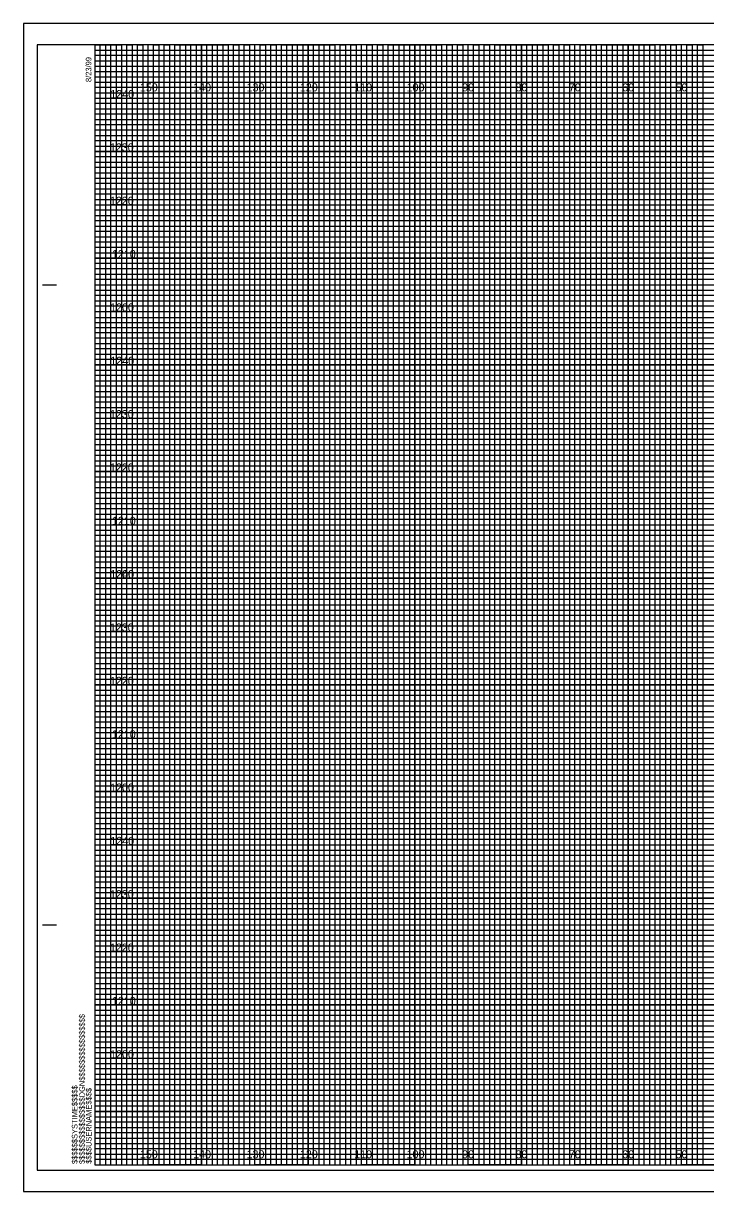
# Model space of a CAD drawing. Extents: x -13 to 323, y -5 to 214.
# Drawn here: x -13.4 to 114.5, y -5 to 214 of the extents above; entities that cross this region are included whole.
import ezdxf

# ---------------------------------------------------------------- set-up
doc = ezdxf.new("R2010")
doc.units = 0
for name, color, linetype in [('Prop XS Elevation Labels', 7, 'Continuous'), ('Prop XS Offset Labels', 7, 'Continuous'), ('Sheet Cross Section CELL', 7, 'Continuous'), ('Sheet Cross Section Grid Major CELL', 7, 'Continuous'), ('Sheet Cross Section Grid Middle CELL', 7, 'Continuous'), ('Sheet Cross Section Grid Minor 1 CELL', 7, 'Continuous'), ('Sheet Cross Section Grid Minor 2 CELL', 7, 'Continuous'), ('Sheet Cutting Line CELL', 7, 'Continuous'), ('Sheet DOT Grid CELL', 7, 'Continuous'), ('Sheet Plot Border Inside CELL', 7, 'Continuous'), ('Sheet Plot Border Outside CELL', 7, 'Continuous')]:
    doc.layers.add(name, color=color, linetype=linetype)

msp = doc.modelspace()

# ---------------------------------------------------------------- linework, layer by layer
at = {"layer": 'Sheet Cross Section CELL'}
for p, q in [((-9.8, 165), (-7.3, 165)), ((-9.7, 165), (-7.2, 165)), ((-9.8, 45), (-7.3, 45)), ((-9.7, 45), (-7.2, 45)), ((0, 0), (0, 0)), ((0, 0), (0, 0)), ((0, 0), (0, 0)), ((0, 0), (0, 0)), ((0, 0), (0, 0)), ((0, 0), (0, 0)), ((0, 0), (0, 0))]:
    msp.add_line(p, q, dxfattribs=at)
msp.add_lwpolyline([(320, 210), (0, 210), (0, 0), (320, 0)], close=True, dxfattribs=at)
at = {"layer": 'Sheet Cross Section Grid Major CELL'}
for p, q in [((10, 210), (0, 210)), ((10, 0), (10, 210)), ((30, 210), (20, 210)), ((20, 210), (20, 0)), ((30, 0), (30, 210)), ((50, 210), (40, 210)), ((40, 210), (40, 0)), ((50, 0), (50, 210)), ((70, 210), (60, 210)), ((60, 210), (60, 0)), ((70, 0), (70, 210)), ((90, 210), (80, 210)), ((80, 210), (80, 0)), ((90, 0), (90, 210)), ((110, 210), (100, 210)), ((100, 210), (100, 0)), ((110, 0), (110, 210)), ((20, 0), (10, 0)), ((40, 0), (30, 0)), ((60, 0), (50, 0)), ((80, 0), (70, 0)), ((100, 0), (90, 0)), ((120, 0), (110, 0))]:
    msp.add_line(p, q, dxfattribs=at)
for points in [[(0, 200), (320, 200), (320, 190), (0, 190)], [(0, 180), (320, 180), (320, 170), (0, 170)], [(0, 160), (320, 160), (320, 150), (0, 150)], [(0, 140), (320, 140), (320, 130), (0, 130)], [(0, 120), (320, 120), (320, 110), (0, 110)], [(0, 100), (320, 100), (320, 90), (0, 90)], [(0, 80), (320, 80), (320, 70), (0, 70)], [(0, 60), (320, 60), (320, 50), (0, 50)], [(0, 40), (320, 40), (320, 30), (0, 30)], [(0, 20), (320, 20), (320, 10), (0, 10)]]:
    msp.add_lwpolyline(points, dxfattribs=at)
at = {"layer": 'Sheet Cross Section Grid Middle CELL'}
for points in [[(0, 210), (5, 210), (5, 0), (15, 0), (15, 210), (25, 210), (25, 0), (35, 0), (35, 210), (45, 210), (45, 0), (55, 0), (55, 210), (65, 210), (65, 0), (75, 0), (75, 210), (85, 210), (85, 0), (95, 0), (95, 210), (105, 210), (105, 0), (115, 0)], [(0, 205), (275, 205)], [(0, 185), (320, 185), (320, 195), (0, 195)], [(0, 165), (320, 165), (320, 175), (0, 175)], [(0, 145), (320, 145), (320, 155), (0, 155)], [(0, 125), (320, 125), (320, 135), (0, 135)], [(0, 105), (320, 105), (320, 115), (0, 115)], [(0, 85), (320, 85), (320, 95), (0, 95)], [(0, 65), (320, 65), (320, 75), (0, 75)], [(0, 45), (320, 45), (320, 55), (0, 55)], [(0, 25), (320, 25), (320, 35), (0, 35)], [(0, 5), (320, 5), (320, 15), (0, 15)]]:
    msp.add_lwpolyline(points, dxfattribs=at)
at = {"layer": 'Sheet Cross Section Grid Minor 1 CELL'}
for p, q in [((0, 209), (260, 209)), ((260, 207.98), (0, 207.98)), ((0, 207.98), (0, 207)), ((0, 207), (260, 207)), ((260, 205.89), (0, 205.89)), ((0, 205.89), (0, 204)), ((0, 204), (320, 204))]:
    msp.add_line(p, q, dxfattribs=at)
for points in [[(0, 203), (270, 203), (320, 203), (320, 202), (0, 202)], [(0, 201), (320, 201), (320, 199), (0, 199)], [(0, 198), (320, 198), (320, 197), (0, 196.98)], [(0, 196), (320, 196), (320, 194), (0, 194)], [(0, 193), (320, 193), (320, 192), (0, 192)], [(0, 191), (320, 191), (320, 189), (0, 189)], [(0, 188), (320, 188), (320, 187), (0, 187)], [(0, 186), (320, 186), (320, 184), (0, 184)], [(0, 183), (320, 183), (320, 182), (0, 182)], [(0, 181), (320, 181), (320, 179), (0, 179)], [(0, 178), (320, 178), (320, 177), (0, 177)], [(0, 176), (320, 176), (320, 173.95), (320, 173), (320, 172), (0, 172)], [(0, 174), (320, 174), (320, 173), (0, 173)], [(0, 171), (320, 171), (320, 169), (0, 169.03)], [(0, 169.03), (320, 169), (320, 168), (0, 168)], [(0, 167), (320, 167), (320, 166), (0, 166)], [(0, 164), (320, 164), (320, 163), (0, 163)], [(0, 162), (320, 162), (320, 161), (0, 161)], [(-0.07, 158.89), (320, 158.89), (320, 157.88), (-0.07, 157.88)], [(0, 157), (320, 157), (320, 156), (0, 156)], [(0, 154), (320, 154), (320, 153), (0, 153)], [(0, 152), (320, 152), (320, 151), (0, 151)], [(0, 149), (320, 149), (320, 148), (0, 148)], [(0, 147), (320, 147), (320, 146), (0, 146)], [(0, 144), (320, 144), (320, 143), (0, 143)], [(0, 142), (320, 142), (320, 141), (0, 141)], [(0, 139), (320, 139), (319.99, 137.98), (0, 138)], [(0, 137), (320, 137), (320, 136), (0, 136)], [(0, 134), (320, 134), (320, 133), (0, 133)], [(0, 132), (320, 132), (320, 131), (0, 131)], [(0, 129), (320, 129), (320, 128), (0, 128)], [(0, 127), (320, 127), (320, 126), (0, 126)], [(0, 124), (320, 124), (320, 123), (0, 123)], [(0, 122), (320, 122), (320, 121), (0, 121)], [(0, 119), (320, 119), (320, 118), (0, 118)], [(0, 116.99), (320.07, 116.91), (320, 116), (0, 116)], [(0, 114), (320, 114), (320, 113), (0, 113)], [(0, 112), (320, 112), (320, 111), (0, 111)], [(0, 109), (320, 109), (320, 108), (0, 108)], [(0, 107), (320, 107), (320, 106), (0, 106)], [(0, 104), (320, 104), (320, 103), (0, 103)], [(0, 102), (320, 102), (320, 101), (0, 101)], [(0, 99), (320, 99), (320, 98), (0, 98)], [(0, 97), (320, 97), (320, 96), (0, 96)], [(0, 94), (320, 94), (320, 93), (0, 93)], [(0, 92), (320, 92), (320, 91), (0, 91)], [(0, 89), (320, 89), (320, 88), (0, 88)], [(0, 87), (320, 87), (320, 86), (0, 86)], [(0, 84), (320, 84), (320, 83), (0, 83)], [(0, 82), (320, 82), (320, 81), (0, 81)], [(0, 79), (320, 79), (319.99, 77.98), (0, 78)], [(0, 77), (320, 77), (320, 76), (0, 76)], [(0, 74), (320, 74), (320, 73), (0, 73)], [(0, 72), (320, 72), (320, 71), (0, 71)], [(0, 69), (320, 69), (320, 68), (0, 68)], [(0, 67), (320, 67), (320, 66), (0, 66)], [(0, 64), (320, 64), (320, 63), (0, 63)], [(0, 62), (320, 62), (320, 61), (0, 61)], [(0, 59), (320, 59), (320, 58), (0, 58)], [(0, 56.99), (320.07, 56.91), (320, 56), (0, 56)], [(0, 54), (320, 54), (320, 53), (0, 53)], [(0, 52), (320, 52), (320, 51), (0, 51)], [(0, 49), (320, 49), (320, 48), (0, 48)], [(0, 47), (320, 47), (320, 46), (0, 46)], [(0, 44), (320, 44), (320, 43), (0, 43)], [(0, 42), (320, 42), (320, 41), (0, 41)], [(0, 39), (320, 39), (320, 38), (0, 38)], [(0, 37), (320, 37), (320, 36), (0, 36)], [(0, 34), (320, 34), (320, 33), (0, 33)], [(0, 32), (320, 32), (320, 31), (0, 31)], [(0, 29), (320, 29), (320, 28), (0, 28)], [(0, 27), (320, 27), (320, 26), (0, 26)], [(0, 24), (320, 24), (320, 23), (0, 23)], [(0, 22), (320, 22), (320, 21), (0, 21)], [(0, 19), (320, 19), (320, 18), (0, 18)], [(0, 17), (320, 17), (320, 16), (0, 16)], [(0, 14), (320, 14), (320, 13), (0, 13)], [(0, 12), (320, 12), (320, 11), (0, 11)], [(0, 9), (320, 9), (320, 8), (0, 8)], [(0, 7), (320, 7), (320, 6), (0, 6)], [(0, 4), (320, 4), (320, 3), (0, 3)], [(0, 2), (320, 2), (320, 1), (0, 1)]]:
    msp.add_lwpolyline(points, dxfattribs=at)
at = {"layer": 'Sheet Cross Section Grid Minor 2 CELL'}
for points in [[(0, 0), (1, 0), (1, 210), (2, 210), (2, 0)], [(2, 0), (3, 0), (3, 210), (4, 210), (4, 0)], [(5, 0), (6, 0), (6, 210), (7, 210), (7, 0)], [(7, 0), (8, 0), (8, 210), (9, 210), (9, 0)], [(10, 0), (11, 0), (11, 210), (12, 210), (12, 0)], [(12, 0), (13, 0), (13, 210), (14, 210), (14, 0)], [(15, 0), (16, 0), (16, 210), (17, 210), (17, 0)], [(17, 0), (18, 0), (18, 210), (19, 210), (19, 0)], [(20, 0), (21, 0), (21, 210), (22, 210), (22, 0)], [(22, 0), (23, 0), (23, 210), (24, 210), (24, 0)], [(25, 0), (26, 0), (26, 210), (27, 210), (27, 0)], [(27, 0), (28, 0), (28, 210), (29, 210), (29, 0)], [(30, 0), (31, 0), (31, 210), (32, 210), (32, 0)], [(32, 0), (33, 0), (33, 210), (34, 210), (34, 0)], [(35, 0), (36, 0), (36, 210), (37, 210), (37, 0)], [(37, 0), (38, 0), (38, 210), (39, 210), (39, 0)], [(40, 0), (41, 0), (41, 210), (42, 210), (42, 0)], [(42, 0), (43, 0), (43, 210), (44, 210), (44, 0)], [(45, 0), (46, 0), (46, 210), (47, 210), (47, 0)], [(47, 0), (48, 0), (48, 210), (49, 210), (49, 0)], [(50, 0), (51, 0), (51, 210), (52, 210), (52, 0)], [(52, 0), (53, 0), (53, 210), (54, 210), (54, 0)], [(55, 0), (56, 0), (56, 210), (57, 210), (57, 0)], [(57, 0), (58, 0), (58, 210), (59, 210), (59, 0)], [(60, 0), (61, 0), (61, 210), (62, 210), (62, 0)], [(62, 0), (63, 0), (63, 210), (64, 210), (64, 0)], [(65, 0), (66, 0), (66, 210), (67, 210), (67, 0)], [(67, 0), (68, 0), (68, 210), (69, 210), (69, 0)], [(70, 0), (71, 0), (71, 210), (72, 210), (72, 0)], [(72, 0), (73, 0), (73, 210), (74, 210), (74, 0)], [(75, 0), (76, 0), (76, 210), (77, 210), (77, 0)], [(77, 0), (78, 0), (78, 210), (79, 210), (79, 0)], [(80, 0), (81, 0), (81, 210), (82, 210), (82, 0)], [(82, 0), (83, 0), (83, 210), (84, 210), (84, 0)], [(85, 0), (86, 0), (86, 210), (87, 210), (87, 0)], [(87, 0), (88, 0), (88, 210), (89, 210), (89, 0)], [(90, 0), (91, 0), (91, 210), (92, 210), (92, 0)], [(92, 0), (93, 0), (93, 210), (94, 210), (94, 0)], [(95, 0), (96, 0), (96, 210), (97, 210), (97, 0)], [(97, 0), (98, 0), (98, 210), (99, 210), (99, 0)], [(100, 0), (101, 0), (101, 210), (102, 210), (102, 0)], [(102, 0), (103, 0), (103, 210), (104, 210), (104, 0)], [(105, 0), (106, 0), (106, 210), (107, 210), (107, 0)], [(107, 0), (108, 0), (108, 210), (109, 210), (109, 0)], [(110, 0), (111, 0), (111, 210), (112, 210), (112, 0)], [(112, 0), (113, 0), (113, 210), (114, 210), (114, 0)]]:
    msp.add_lwpolyline(points, dxfattribs=at)
at = {"layer": 'Sheet Cutting Line CELL'}
for p, q in [((323.3, 214), (-13.4, 214)), ((-13.4, 214), (-13.4, -5)), ((-13.4, -5), (323.3, -5))]:
    msp.add_line(p, q, dxfattribs=at)
at = {"layer": 'Sheet DOT Grid CELL'}
for p, q in [((10, 0), (10, 210)), ((20, 0), (20, 210)), ((30, 0), (30, 210)), ((40, 0), (40, 210)), ((50, 0), (50, 210)), ((60, 0), (60, 210)), ((70, 0), (70, 210)), ((80, 0), (80, 210)), ((90, 0), (90, 210)), ((100, 0), (100, 210)), ((110, 0), (110, 210)), ((0, 200), (320, 200)), ((0, 190), (320, 190)), ((0, 180), (320, 180)), ((0, 170), (320, 170)), ((0, 160), (320, 160)), ((0, 150), (320, 150)), ((0, 140), (320, 140)), ((0, 130), (320, 130)), ((0, 120), (320, 120)), ((0, 110), (320, 110)), ((0, 100), (320, 100)), ((0, 90), (320, 90)), ((0, 80), (320, 80)), ((0, 70), (320, 70)), ((0, 60), (320, 60)), ((0, 50), (320, 50)), ((0, 40), (320, 40)), ((0, 30), (320, 30)), ((0, 20), (320, 20)), ((0, 10), (320, 10))]:
    msp.add_line(p, q, dxfattribs=at)
at = {"layer": 'Sheet Plot Border Inside CELL'}
msp.add_lwpolyline([(-10.8, -1), (322.4, -1), (322.4, 210), (-10.8, 210)], close=True, dxfattribs=at)
at = {"layer": 'Sheet Plot Border Outside CELL'}
msp.add_lwpolyline([(-13.4, -5), (323.3, -5), (323.3, 214), (-13.4, 214)], close=True, dxfattribs=at)

# ---------------------------------------------------------------- texts
at = {"layer": 'Prop XS Elevation Labels'}
for s, p in [('1240', (2.9, 200)), ('1230', (2.82, 190)), ('1220', (2.83, 180)), ('1210', (3.2, 170)), ('1200', (2.87, 160)), ('1240', (2.9, 150)), ('1230', (2.82, 140)), ('1220', (2.83, 130)), ('1210', (3.2, 120)), ('1200', (2.87, 110)), ('1240', (2.9, 110)), ('1230', (2.82, 100)), ('1220', (2.83, 90)), ('1210', (3.2, 80)), ('1200', (2.87, 70)), ('1240', (2.9, 60)), ('1230', (2.82, 50)), ('1220', (2.83, 40)), ('1210', (3.2, 30)), ('1200', (2.87, 20))]:
    msp.add_text(s, height=1.5, dxfattribs=at).set_placement(p)
at = {"layer": 'Prop XS Offset Labels'}
for s, p in [('150', (8.44, 201.25)), ('140', (18.44, 201.25)), ('130', (28.44, 201.25)), ('120', (38.44, 201.25)), ('110', (48.62, 201.25)), ('100', (58.44, 201.25)), ('90', (68.86, 201.25)), ('80', (78.86, 201.25)), ('70', (88.86, 201.25)), ('60', (98.86, 201.25)), ('50', (108.86, 201.25)), ('150', (8.44, 1.25)), ('140', (18.44, 1.25)), ('130', (28.44, 1.25)), ('120', (38.44, 1.25)), ('110', (48.62, 1.25)), ('100', (58.44, 1.25)), ('90', (68.86, 1.25)), ('80', (78.86, 1.25)), ('70', (88.86, 1.25)), ('60', (98.86, 1.25)), ('50', (108.86, 1.25))]:
    msp.add_text(s, height=1.5, dxfattribs=at).set_placement(p)
at = {"layer": 'Sheet Cross Section CELL'}
for s, p in [('8/23/99', (-0.65, 203)), ('$$$$$$$$$$$$$$$$DGN$$$$$$$$$$$$$$$$', (-1.88, 0.18)), ('$$$$$$SYSTIME$$$$$', (-3.26, 0.18)), ('$$$$USERNAME$$$$', (-0.62, 0.23))]:
    msp.add_text(s, height=1.05, rotation=90, dxfattribs=at).set_placement(p)

doc.saveas('drawing.dxf')
